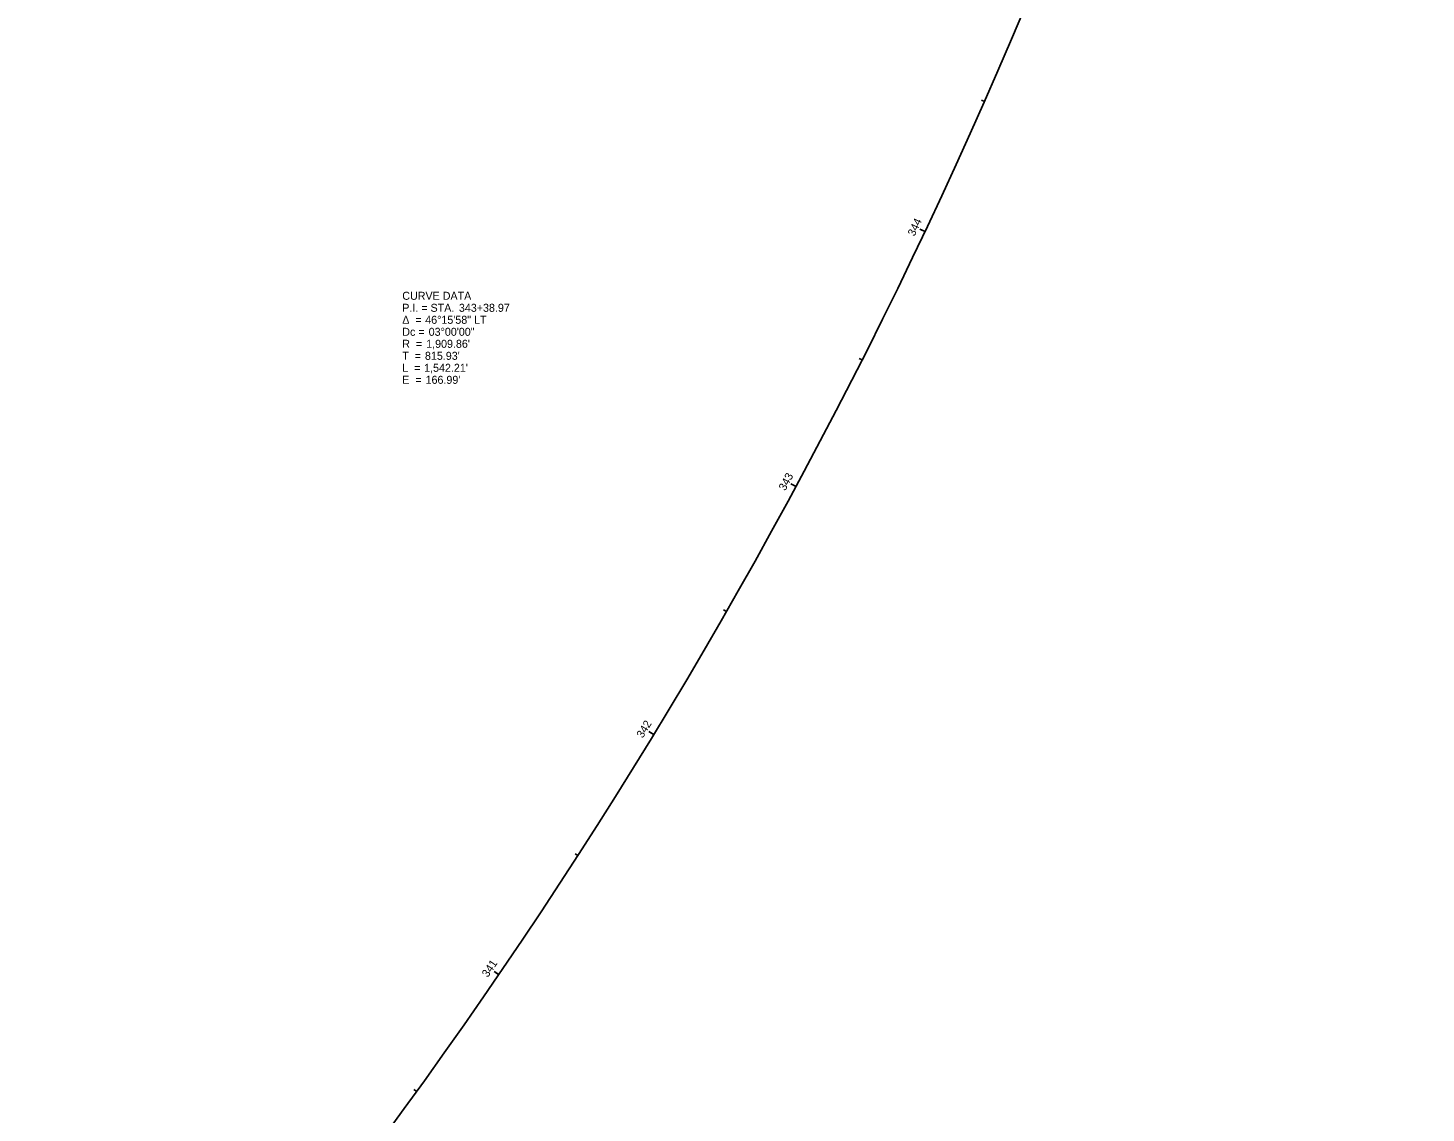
# Model space of a CAD drawing. Extents: x 1380776 to 1381901, y 503546 to 507267.
# Drawn here: x 1381260.3 to 1381749.3, y 504083.6 to 504463.2 of the extents above; entities that cross this region are included whole.
import ezdxf

# ---------------------------------------------------------------- set-up
doc = ezdxf.new("R2010")
doc.units = 0
for name, color, linetype in [('_CIVIL_CONSTRUCTION', 7, 'Continuous'), ('DR_X_Cells', 7, 'Continuous'), ('DR_X_Storm_Sewer', 7, 'Continuous'), ('GK_Drainage_Nodes', 7, 'Continuous'), ('SC_Scratch1', 7, 'Continuous'), ('SC_Scratch3', 7, 'Continuous')]:
    doc.layers.add(name, color=color, linetype=linetype)

msp = doc.modelspace()

# ---------------------------------------------------------------- linework, layer by layer
at = {"layer": '_CIVIL_CONSTRUCTION'}
for p, q in [((1381574.08, 504391.99), (1381573, 504392.5)), ((1381528.95, 504302.77), (1381527.89, 504303.34)), ((1381479.21, 504216.03), (1381478.18, 504216.65)), ((1381424.99, 504132.01), (1381424, 504132.69))]:
    msp.add_line(p, q, dxfattribs=at)
at = {"layer": 'DR_X_Storm_Sewer'}
for p, q in [((1381594.88, 504437.46), (1381593.78, 504437.94)), ((1381574.08, 504391.99), (1381572.27, 504392.84)), ((1381552.1, 504347.08), (1381551.03, 504347.62)), ((1381528.95, 504302.77), (1381527.19, 504303.72)), ((1381504.64, 504259.07), (1381503.6, 504259.67)), ((1381479.21, 504216.03), (1381477.5, 504217.07)), ((1381452.65, 504173.66), (1381451.64, 504174.31)), ((1381424.99, 504132.01), (1381423.34, 504133.14)), ((1381396.26, 504091.1), (1381395.28, 504091.8))]:
    msp.add_line(p, q, dxfattribs=at)
at = {"layer": 'SC_Scratch1'}
msp.add_arc((1379847.87, 505209.16), 1909.86, 308.35888, 354.62505, dxfattribs=at)
msp.add_arc((1379847.87, 505209.16), 1909.86, 308.35888, 354.62505, dxfattribs=at)

# ---------------------------------------------------------------- texts
at = {"layer": 'DR_X_Cells'}
for s, p in [('CURVE DATA', (1381391.22, 504368.11)), ('Δ  = ', (1381391.22, 504359.71)), ('P.I. = STA. ', (1381391.22, 504363.91)), ('46°15\'58" LT', (1381399.24, 504359.71)), ('343+38.97', (1381411.03, 504363.91)), ('Dc = ', (1381391.22, 504355.51)), ('03°00\'00"', (1381400.45, 504355.51)), ('R  = ', (1381391.22, 504351.31)), ("1,909.86'", (1381399.58, 504351.31)), ('T  = ', (1381391.22, 504347.11)), ("815.93'", (1381399.15, 504347.11)), ('L  = ', (1381391.22, 504342.91)), ("1,542.21'", (1381398.86, 504342.91)), ('E  = ', (1381391.22, 504338.71)), ("166.99'", (1381399.37, 504338.71))]:
    msp.add_text(s, height=2.8, dxfattribs=at).set_placement(p)
at = {"layer": 'DR_X_Storm_Sewer'}
for s, rotation, p in [('344', 64.6677, (1381570.38, 504390.12)), ('343', 61.6677, (1381525.16, 504301.09)), ('342', 58.6677, (1381475.33, 504214.55)), ('341', 55.6677, (1381421.12, 504130.84))]:
    msp.add_text(s, height=2.8, rotation=rotation, dxfattribs=at).set_placement(p)
at = {"layer": 'GK_Drainage_Nodes'}
for s, p in [('CURVE DATA', (1381391.22, 504368.11)), ('Δ  = ', (1381391.22, 504359.71)), ('P.I. = STA. ', (1381391.22, 504363.91)), ('46°15\'58" LT', (1381399.24, 504359.71)), ('343+38.97', (1381411.03, 504363.91)), ('Dc = ', (1381391.22, 504355.51)), ('03°00\'00"', (1381400.45, 504355.51)), ('R  = ', (1381391.22, 504351.31)), ("1,909.86'", (1381399.58, 504351.31)), ('T  = ', (1381391.22, 504347.11)), ("815.93'", (1381399.15, 504347.11)), ('L  = ', (1381391.22, 504342.91)), ("1,542.21'", (1381398.86, 504342.91)), ('E  = ', (1381391.22, 504338.71)), ("166.99'", (1381399.37, 504338.71))]:
    msp.add_text(s, height=2.8, dxfattribs=at).set_placement(p)
at = {"layer": 'SC_Scratch3'}
for s, p in [('CURVE DATA', (1381391.22, 504368.11)), ('Δ  = ', (1381391.22, 504359.71)), ('P.I. = STA. ', (1381391.22, 504363.91)), ('46°15\'58" LT', (1381399.24, 504359.71)), ('343+38.97', (1381411.03, 504363.91)), ('Dc = ', (1381391.22, 504355.51)), ('03°00\'00"', (1381400.45, 504355.51)), ('R  = ', (1381391.22, 504351.31)), ("1,909.86'", (1381399.58, 504351.31)), ('T  = ', (1381391.22, 504347.11)), ("815.93'", (1381399.15, 504347.11)), ('L  = ', (1381391.22, 504342.91)), ("1,542.21'", (1381398.86, 504342.91)), ('E  = ', (1381391.22, 504338.71)), ("166.99'", (1381399.37, 504338.71))]:
    msp.add_text(s, height=2.8, dxfattribs=at).set_placement(p)

doc.saveas('drawing.dxf')
